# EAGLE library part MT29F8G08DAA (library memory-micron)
4Gb, 8Gb, and 16Gb x8 NAND Flash Memory Source: http://download.micron.com/pdf/datasheets/flash/nand/4gb_nand_m40a.pdf
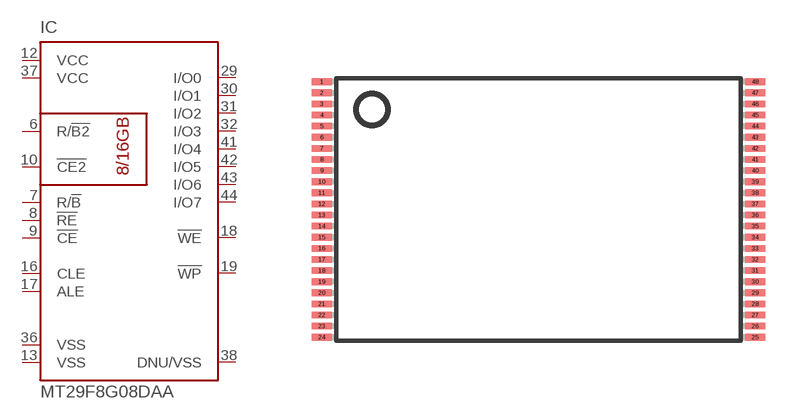
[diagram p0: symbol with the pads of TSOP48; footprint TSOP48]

Designator prefix IC

## MT29F8G08DAA (OC_FARNELL: unknown; OC_NEWARK: unknown)  [TSOP48]
6  R/!B2  pas
7  R/!B  in
8  !RE  in
9  !CE  in
10  !CE2  pas
12  VCC  pwr
13  VSS  pwr
16  CLE  in
17  ALE  in
18  !WE  in
19  !WP  in
25  DNU  nc
26  DNU  nc
29  I/O0
30  I/O1
31  I/O2
32  I/O3
36  VSS  pwr
37  VCC  pwr
38  DNU/VSS  pas
41  I/O4
42  I/O5
43  I/O6
44  I/O7
48  DNU  nc

## Footprint TSOP48 (pad centres in mm)
48-Pin TSOP OCPL Type 1 (WC Package Code) Source: http://download.micron.com/pdf/datasheets/flash/nand/4gb_nand_m40a.pdf
smd 0.9 x 0.3: 1 -9.75,5.75; 2 -9.75,5.25; 3 -9.75,4.75; 4 -9.75,4.25; 5 -9.75,3.75; 6 -9.75,3.25; 7 -9.75,2.75; 8 -9.75,2.25; 9 -9.75,1.75; 10 -9.75,1.25; 11 -9.75,0.75; 12 -9.75,0.25; 13 -9.75,-0.25; 14 -9.75,-0.75; 15 -9.75,-1.25; 16 -9.75,-1.75; 17 -9.75,-2.25; 18 -9.75,-2.75; 19 -9.75,-3.25; 20 -9.75,-3.75; 21 -9.75,-4.25; 22 -9.75,-4.75; 23 -9.75,-5.25; 24 -9.75,-5.75; 25 9.75,-5.75; 26 9.75,-5.25; 27 9.75,-4.75; 28 9.75,-4.25; 29 9.75,-3.75; 30 9.75,-3.25; 31 9.75,-2.75; 32 9.75,-2.25; 33 9.75,-1.75; 34 9.75,-1.25; 35 9.75,-0.75; 36 9.75,-0.25; 37 9.75,0.25; 38 9.75,0.75; 39 9.75,1.25; 40 9.75,1.75; 41 9.75,2.25; 42 9.75,2.75; 43 9.75,3.25; 44 9.75,3.75; 45 9.75,4.25; 46 9.75,4.75; 47 9.75,5.25; 48 9.75,5.75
